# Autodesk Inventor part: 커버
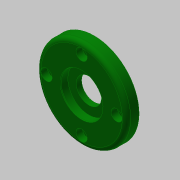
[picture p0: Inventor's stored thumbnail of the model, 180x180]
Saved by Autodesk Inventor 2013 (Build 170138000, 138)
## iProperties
Created: 2019-06
Part Number: 커버
Material: 알루미늄 6061
Document SubType Name: Modeling
Designer: mduedu
Density: 1 g/cm^3
Author: mduedu
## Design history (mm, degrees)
sketch "스케치1"
  geometry: L1 (0, 0)-(9, 0); L2 (9, 0)-(9, 32); L3 (9, 32)-(0, 32); L4 (0, 32)-(0, 0); L5 (9, 0)-(12, 0); L6 (12, 0)-(12, 20); L7 (12, 20)-(9, 20); L8 (9, 20)-(9, 0)
  constraints: 16 end point, 4 parallel, 2 horizontal, 2 perpendicular
  dimensions: "d0" = 64 diameter of L3 L1; "d2" = 40 diameter of L7 L5; "d3" = 12 distance between parallel lines of L6 L4; "d4" = 3 distance between parallel lines of L2 L6
revolve "회전1" sketch "스케치1" stored, may be unused: angle "d5" = 90 deg
sketch "스케치2"
  geometry: L1 (0, 0)-(5.2, 0); L2 (5.2, 0)-(5.2, 15); L3 (5.2, 15)-(0, 15); L4 (0, 15)-(0, 0); L5 (5.2, 0)-(9, 0); L6 (9, 0)-(9, 9); L7 (9, 9)-(5.2, 9); L8 (5.2, 9)-(5.2, 0); L9 (9, 0)-(12, 0); L10 (12, 0)-(12, 15); L11 (12, 15)-(9, 15); L12 (9, 15)-(9, 0); L13 (12, -20)-(12, 20) reference
  constraints: 24 end point, 6 parallel, 3 horizontal, 3 perpendicular, 1 collinear
  dimensions: "d6" = 30 diameter of L3 L1; "d8" = 30 diameter of L11 L9; "d9" = 18 diameter of L7 L5; "d10" = 5.2 distance of L2.end L3.end; "d11" = 3 distance between parallel lines of L10 L12
revolve "회전2" sketch "스케치2" stored, may be unused: angle "d12" = 90 deg
fillet "모깎기1" dims "d13" = 3
fillet "모깎기2" dims "d14" = 3
chamfer "모따기1" distance "d15" = 1; stored, may be unused: second distance "d16" = 2, angle "d17" = 45 deg
sketch "스케치3" dims "d18" = 50
  geometry: 3 further points
  constraints: 2 vertical alignment, 1 coincident, 2 other
hole "구멍1" sketch "스케치3" at (0, 25) diameter "d19" = 4.5; stored, may be unused: countersink angle "d23" = 90 deg, drill point angle "d25" = 118 deg; dims "d20" = 6, "d21" = 8, "d22" = 4.6, "d24" = 8
chamfer "모따기2" distance "d29" = 0.5; stored, may be unused: second distance "d30" = 2, angle "d31" = 30 deg
node "솔리드1"
pattern_circular "원형 패턴1" dims angle "d27" = 360 deg
